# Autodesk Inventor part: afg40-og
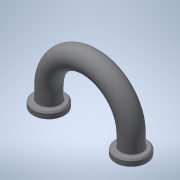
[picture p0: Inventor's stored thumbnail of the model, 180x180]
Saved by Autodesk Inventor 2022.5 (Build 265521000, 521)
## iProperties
Created: 2016-12
Part Number: afg40-og
Material: 一般
Document SubType Name: Modeling
Designer: imaocorp
Density: 1 g/cm^3
Appearance: 既定
Author: imaocorp
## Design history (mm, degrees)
node "afg40-og.x_t1"
node "afg40-og"
node "Base1"
